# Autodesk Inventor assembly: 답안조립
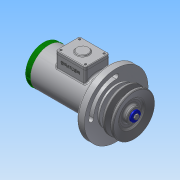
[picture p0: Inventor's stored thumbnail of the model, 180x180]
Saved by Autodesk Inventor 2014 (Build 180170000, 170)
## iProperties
Created: 2017-05
Part Number: 답안조립
Document SubType Name: Assembly
Designer: user
Author: user
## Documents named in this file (18)
- C:\Users\user\Desktop\470508V1013\답안조립.iam
- C:\Users\user\Desktop\470508V1013\1-본체.ipt
- C:\Users\user\Desktop\470508V1013\사이드 커버.ipt
- 사이드 커버.ipt
- C:\Users\user\Desktop\470508V1013\탑 커버.ipt
- C:\Users\user\Desktop\470508V1013\축.ipt
- C:\Users\user\Desktop\470508V1013\너트 M10.ipt
- C:\Users\user\Desktop\470508V1013\와셔 10x21.ipt
- C:\Users\user\Desktop\470508V1013\부시1.ipt
- C:\Users\user\Desktop\470508V1013\멈춤링 15 x 1.ipt
- C:\Users\user\Desktop\470508V1013\베어링 15 x 35 x 11.ipt
- C:\Users\user\Desktop\470508V1013\멈춤링 35x1.6.ipt
- C:\Users\user\Desktop\470508V1013\부시2.ipt
- C:\Users\user\Desktop\470508V1013\오일 실 15 25 7.ipt
- C:\Users\user\Desktop\470508V1013\키 4 x 4 x 18.ipt
- C:\Users\user\Desktop\470508V1013\와셔 4x16.ipt
- C:\Users\user\Desktop\470508V1013\볼트 M4 x 10.ipt
- C:\Users\user\Desktop\470508V1013\V-벨트풀리.ipt
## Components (3 placed, 3 different names)
1. 1-본체:1 — Mate:1, Mate:2, Mate:3, Mate:4, Mate:5, Mate:6, Mate:26, Mate:34
2. ISO 4017 M4 x 10:1 — Insert:1
3. V-벨트풀리:1 — Mate:30, Angle:1, Mate:31
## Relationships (12: Mate 10, Angle 1, Insert 1)
- Mate:1: 1-본체:1
- Mate:2: 1-본체:1
- Mate:3: 1-본체:1
- Mate:4: 1-본체:1
- Mate:5: 1-본체:1
- Mate:6: 1-본체:1
- Mate:26: 1-본체:1
- Mate:30: V-벨트풀리:1
- Angle:1: V-벨트풀리:1
- Mate:31: V-벨트풀리:1
- Insert:1: ISO 4017 M4 x 10:1
- Mate:34: 1-본체:1
